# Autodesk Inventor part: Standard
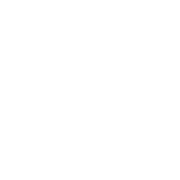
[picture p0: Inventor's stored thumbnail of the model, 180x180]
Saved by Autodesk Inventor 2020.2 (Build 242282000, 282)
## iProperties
Created: 2018-03
Part Number: Standard
Material: Ogólny
Document SubType Name: Modeling
Density: 1 g/cm^3
Appearance: Domyślna
Designer: F.Stasiak
Manager: www.cadconsulting.pl
Company: Fabian Stasiak CAD Consulting
Author: F.Stasiak
Subject: Zbiór ćwiczeń. Autodesk Inventor 2020. Kurs podstawowy
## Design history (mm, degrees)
